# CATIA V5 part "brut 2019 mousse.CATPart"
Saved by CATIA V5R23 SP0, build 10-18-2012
Part number: 1-carrosserie SG
Bounding box of the stored display mesh (mm): x -50 to 50, y -39 to 261, z -21 to 57
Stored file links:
  E:\jules richard\Course en cours 2019-2020\Bloc Propulseur CEC 2019 V4\mousse boitier\brute 2018 mousse.CATPart
  Y:\SECSI\voiture eclipse\voiture eclipse.CATProduct
  Y:\SECSI\voiture eclipse\carrosserie.CATPart
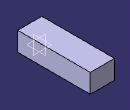
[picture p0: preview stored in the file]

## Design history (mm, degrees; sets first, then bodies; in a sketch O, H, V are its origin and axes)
Set1
  DatumCurve1
Body1 (main body)
  Sketch1 on yz-plane, origin (0, 0, 0), H (0, 1, 0), V (0, 0, 1)
    line L1 (-39, 57) -> (261, 57)
    line L2 (261, 57) -> (261, -21)
    line L3 (261, -21) -> (-39, -21)
    line L4 (-39, -21) -> (-39, 57)
    distance L1 L3 = 78
    distance L2 L4 = 300
    distance V L4 = 39
    distance H L3 = 21
    horizontal: L1 H, L3 H
    vertical: L2 V, L4 V
  Pad1: profile Sketch1, direction (1, 0, 0), length 50, mirrored extent
  Sketch2 on face of Pad1 from Sketch1.L3, origin (0, 0, -21), H (1, 0, 0), V (0, -1, 0)
    line L1 (-25, 19) -> (25, 19)
    line L2 (25, 19) -> (25, -91.5)
    line L3 (22, -94.5) -> (-22, -94.5)
    line L4 (-25, -91.5) -> (-25, 19)
    arc A1 centre (22, -91.5) radius 3 from (25, -91.5) to (22, -94.5) cw
    arc A2 centre (-22, -91.5) radius 3 from (-25, -91.5) to (-22, -94.5) ccw
    distance L4 L2 = 50
    distance V L4 = 25
    distance L1 L3 = 113.5
    radius A1 = 3
    radius A2 = 3
    distance H L1 = 19
    horizontal: L1 H, L3 H
    vertical: L2 V, L4 V
    tangency: A1 L2, A1 L3, A2 L4, A2 L3
  Pocket1: profile Sketch2, direction (0, 0, 1), length 43
  Sketch3 on face of Pad1 from Sketch1.L3, origin (0, 0, -21), H (1, 0, 0), V (0, -1, 0)
    line L1 (-21, -94.5) -> (21, -94.5)
    line L2 (21, -94.5) -> (21, -201.5)
    line L3 (18, -204.5) -> (-18, -204.5)
    line L4 (-21, -201.5) -> (-21, -94.5)
    reference projected line E1 (-20, -94.5) -> (20, -94.5) from edge [face of Pad1 from Sketch1.L3 | face of Pocket1 from Sketch2.L3]
    arc A1 centre (-18, -201.5) radius 3 from (-18, -204.5) to (-21, -201.5) cw
    arc A2 centre (18, -201.5) radius 3 from (21, -201.5) to (18, -204.5) cw
    distance L3 L1 = 110
    radius A1 = 3
    radius A2 = 3
    distance L2 L4 = 42
    distance L4 V = 21
    horizontal: L1 H, L3 H
    vertical: L2 V, L4 V
    coincidence: L1 E1
    tangency: A1 L3, A1 L4, A2 L2, A2 L3
  Pocket2: profile Sketch3, direction (0, 0, 1), length 27
  Sketch4 on face of Pad1 from Sketch1.L3, origin (0, 0, -21), H (1, 0, 0), V (0, -1, 0)
    line L1 (-25, 39) -> (25, 39)
    line L2 (25, 39) -> (25, 22)
    line L3 (22, 19) -> (-22, 19)
    line L4 (-25, 22) -> (-25, 39)
    reference projected line E1 (-52.5, 39) -> (52.5, 39) from edge [face of Pad1 from Sketch1.L4 | face of Pad1 from Sketch1.L1]
    reference projected line E2 (20, 19) -> (-20, 19) from edge [end face of Pocket1 | face of Pocket1 from Sketch2.L1]
    arc A1 centre (-22, 22) radius 3 from (-25, 22) to (-22, 19) ccw
    arc A2 centre (22, 22) radius 3 from (22, 19) to (25, 22) ccw
    distance L4 L2 = 50
    distance V L2 = 25
    radius A1 = 3
    radius A2 = 3
    horizontal: L1 H, L3 H
    vertical: L2 V, L4 V
    coincidence: L1 E1, L3 E2
    tangency: A1 L4, A1 L3, A2 L3, A2 L2
  Pocket3: profile Sketch4, direction (0, 0, 1), length 38
  Sketch5 on end face of Pocket1, origin (0, 0, 22), H (1, 0, 0), V (0, -1, 0)
    arc A1 centre (-25, -44.5) radius 5 from (-25, -49.5) to (-25, -39.5) ccw
    point P1 (-25, -44.5)
    arc A2 centre (25, -44.5) radius 5 from (25, -39.5) to (25, -49.5) ccw
    point P2 (25, -44.5)
    reference projected line E1 (25, -91) -> (25, 19) from edge [face of Pad1 from Sketch1.L3 | face of Pocket1 from Sketch2.L2]
    reference projected line E2 (-25, 19) -> (-25, -91) from edge [face of Pad1 from Sketch1.L3 | face of Pocket1 from Sketch2.L4]
    line L1 (25, -39.5) -> (25, -49.5)
    line L2 (-25, -39.5) -> (-25, -49.5)
    reference projected line E3 (25, -91) -> (25, 19) from edge [face of Pad1 from Sketch1.L3 | face of Pocket1 from Sketch2.L2]
    reference projected line E4 (-25, 19) -> (-25, -91) from edge [face of Pad1 from Sketch1.L3 | face of Pocket1 from Sketch2.L4]
    reference projected line E5 (19.5, -94.5) -> (-19.5, -94.5) from edge [face of Pocket1 from Sketch2.L3 | end face of Pocket2]
    reference projected line E6 (19.5, -94.5) -> (-19.5, -94.5) from edge [face of Pocket1 from Sketch2.L3 | end face of Pocket2]
    radius A2 = 5
    radius A1 = 5
    distance P2 E5 = 50
    distance P1 E6 = 50
    coincidence: E1 P2, P1 E2, L1 E3, L2 E4
    vertical: L1 V, L2 V
  Pad2: profile Sketch5, direction (0, 0, -1), length 36
  Fillet1: radius 3, on edge [face of Pocket1 from Sketch2.L2 | face of Pad2 from Sketch5.A2]; edge [face of Pad2 from Sketch5.A2 | face of Pocket1 from Sketch2.L2]; edge [face of Pad2 from Sketch5.A1 | face of Pocket1 from Sketch2.L4]; edge [face of Pocket1 from Sketch2.L4 | face of Pad2 from Sketch5.A1]
  Sketch6 on face of Pad1 from Sketch1.L3, origin (0, 0, -21), H (1, 0, 0), V (0, -1, 0)
    line L1 (-25, 22) -> (25, 22)
    line L2 (25, 22) -> (25, 12)
    line L3 (25, 12) -> (-25, 12)
    line L4 (-25, 12) -> (-25, 22)
    reference projected line E1 (25, 22) -> (25, 39) from edge [face of Pad1 from Sketch1.L3 | face of Pocket3 from Sketch4.L2]
    reference projected line E2 (-25, 39) -> (-25, 22) from edge [face of Pad1 from Sketch1.L3 | face of Pocket3 from Sketch4.L4]
    distance L3 L1 = 10
    distance L3 H = 12
    horizontal: L1 H, L3 H
    vertical: L2 V, L4 V
    coincidence: L2 E1, E2 L4
  Pocket4: profile Sketch6, direction (0, 0, 1), up to end face of Pocket3
  Fillet2: radius 3, on edge [face of Pocket1 | face of Pocket1 from Sketch2.L1]; edge [face of Pocket1 from Sketch2.L1 | face of Pocket1]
